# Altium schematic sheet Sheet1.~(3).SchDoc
size A4
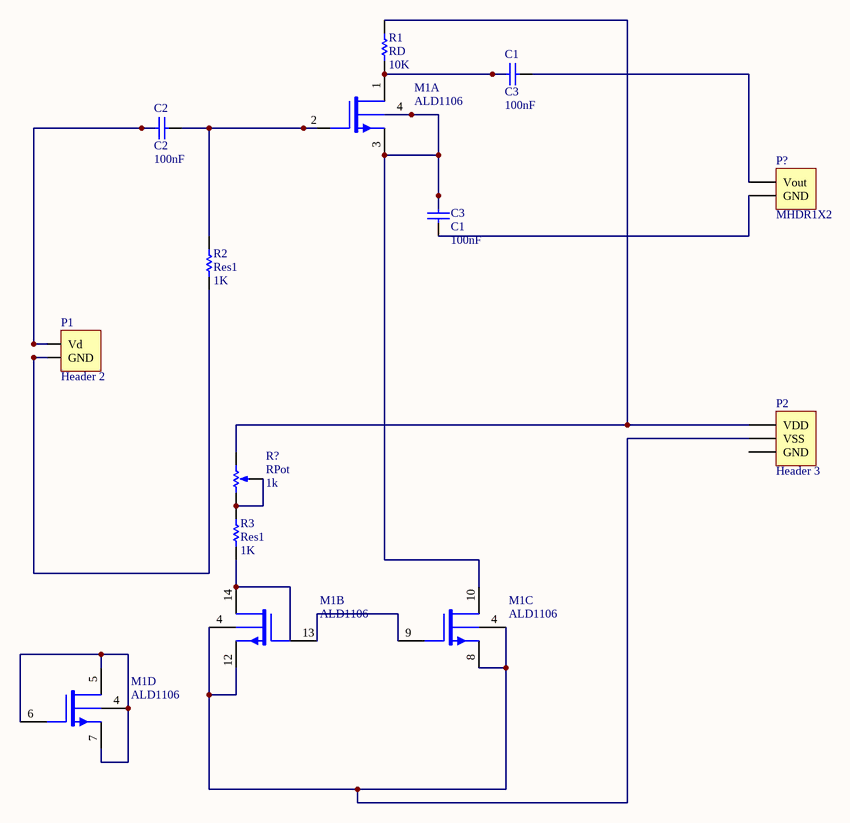
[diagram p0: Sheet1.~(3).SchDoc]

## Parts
C1  C3  value 100nF  [RAD-0.3]
C2  C2  value 100nF  [RAD-0.3]
C3  C1  value 100nF  [RAD-0.3]
M1  ALD1106  [DIP-14]  (parts A,B,C,D of 4)
P1  Header 2  [HDR1X2]
P2  Header 3  [HDR1X3]
P?  MHDR1X2  [MHDR1X2]
R1  RD  value 10K  [AXIAL-0.3]
R2  Res1  value 1K  [AXIAL-0.3]
R3  Res1  value 1K  [AXIAL-0.3]
R?  RPot  value 1k  [VR5]

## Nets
NetC1_1: C1.1 M1.1(DN1) R1.1
NetC1_2: C1.2 P?.1(Vout)
NetC2_1: C2.1 P1.1(Vd)
NetC2_2: C2.2 M1.2(GN1) R2.2
NetC3_1: C3.1 P?.2(GND)
NetC3_2: C3.2 M1.3(SN1) M1.4(V-) M1.10(DN3)
NetM1_4: M1.4(V-) M1.8(SN3) M1.12(SN2) P2.2(VSS)
NetM1_4: M1.4(V-) M1.5(DN4) M1.6(GN4) M1.7(SN4)  [a separate net that carries the same name]
NetM1_9: M1.9(GN3) M1.13(GN2)
NetM1_14: M1.14(DN2) R3.1
NetP1_2: P1.2(GND) R2.1
NetP2_1: P2.1(VDD) R1.2 R?.3(BOT)
NetR3_2: R3.2 R?.1(TOP) R?.2(TAP)

Not connected (* = marked no-connect by the designer): P2 3(GND)

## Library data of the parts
C1-C3 = Cap: Capacitor
M1 = ALD1106: Quad N-channel matched MOSFET array
P1 = Header 2: Header, 2-Pin
P2 = Header 3: Header, 3-Pin
P? = MHDR1X2: Header, 2-Pin
R1-R3 = Res1: Resistor
R? = RPot: Potentiometer; Sim Note: Enter the Resistance value and the set point into parameter fields.; Set Position: 0.5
